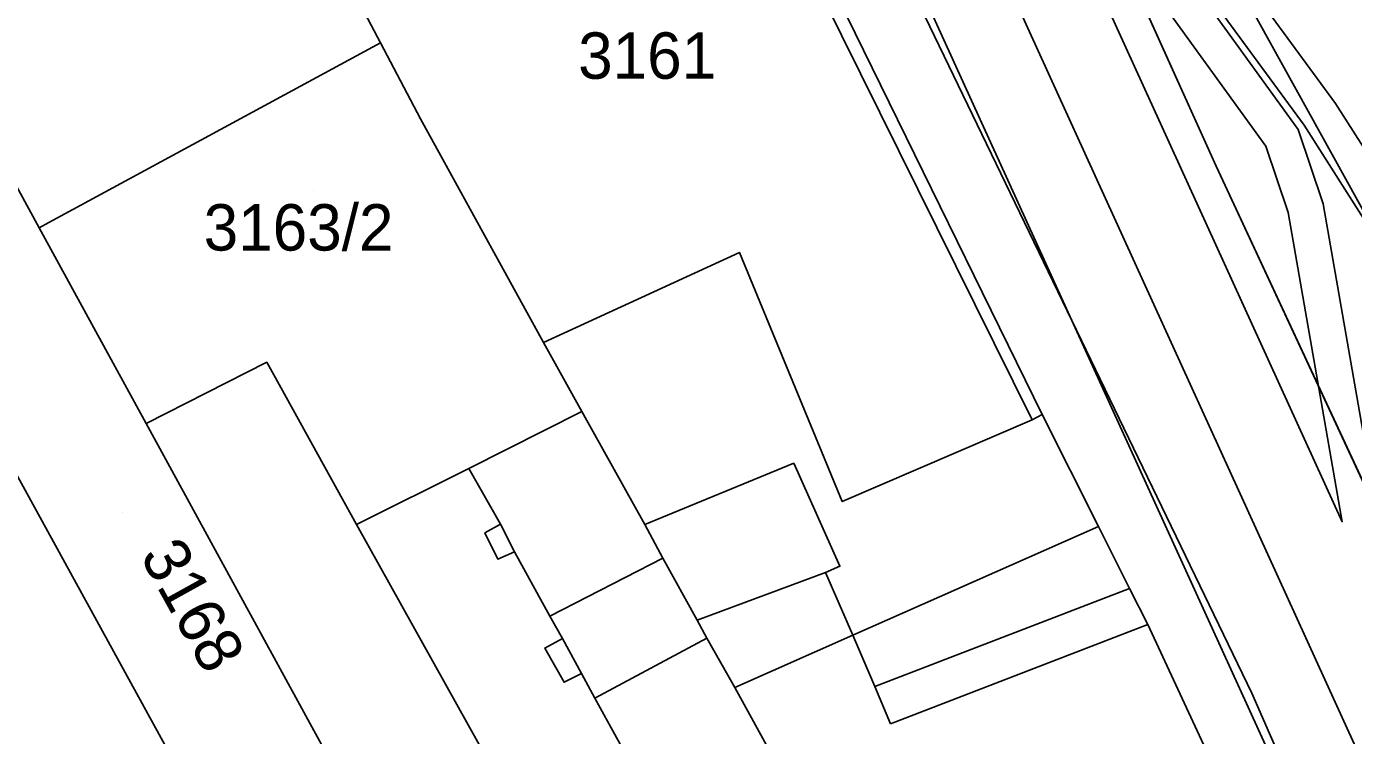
# Model space of a CAD drawing. Extents: x -264070 to -262271, y -1238894 to -1238141.
# Drawn here: x -262970.7 to -262913.5, y -1238536.4 to -1238505.8 of the extents above; entities that cross this region are included whole.
import ezdxf

# ---------------------------------------------------------------- set-up
doc = ezdxf.new("R2010")
doc.units = 0
for name, color, linetype in [('body_kn', 7, 'Continuous'), ('kladpar_druhypozemkov', 7, 'Continuous'), ('kladpar_hranice', 7, 'Continuous'), ('kladpar_parcelnecisla', 7, 'Continuous'), ('kladpar_plochy', 7, 'Continuous'), ('tarchy_linie', 7, 'Continuous'), ('zappar_hrandruhpozemk', 7, 'Continuous')]:
    doc.layers.add(name, color=color, linetype=linetype)

msp = doc.modelspace()

# ---------------------------------------------------------------- linework, layer by layer
at = {"layer": 'body_kn'}
for p, q in [((-262955.44, -1238506.52), (-262955.44, -1238506.52)), ((-262955.44, -1238506.52), (-262955.44, -1238506.52)), ((-262914.29, -1238509.13), (-262914.29, -1238509.13)), ((-262953.72, -1238509.79), (-262953.72, -1238509.79)), ((-262915.89, -1238510.25), (-262915.89, -1238510.25)), ((-262915.64, -1238510.07), (-262915.64, -1238510.07)), ((-262917.28, -1238510.97), (-262917.28, -1238510.97)), ((-262919.42, -1238511.83), (-262919.42, -1238511.83)), ((-262914.81, -1238513.45), (-262914.81, -1238513.45)), ((-262969.73, -1238514.26), (-262969.73, -1238514.26)), ((-262916.32, -1238513.83), (-262916.32, -1238513.83)), ((-262970.15, -1238514.49), (-262970.15, -1238514.49)), ((-262939.97, -1238515.55), (-262939.97, -1238515.55)), ((-262968.71, -1238517.12), (-262968.71, -1238517.12)), ((-262948.41, -1238519.43), (-262948.41, -1238519.43)), ((-262960.34, -1238520.28), (-262960.34, -1238520.28)), ((-262965.54, -1238522.92), (-262965.54, -1238522.92)), ((-262965.54, -1238522.92), (-262965.54, -1238522.92)), ((-262946.76, -1238522.4), (-262946.76, -1238522.4)), ((-262927.36, -1238522.76), (-262927.36, -1238522.76)), ((-262927.36, -1238522.76), (-262927.36, -1238522.76)), ((-262926.92, -1238522.53), (-262926.92, -1238522.53)), ((-262926.92, -1238522.53), (-262926.92, -1238522.53)), ((-262937.63, -1238524.63), (-262937.63, -1238524.63)), ((-262951.63, -1238524.86), (-262951.63, -1238524.86)), ((-262935.54, -1238526.28), (-262935.54, -1238526.28)), ((-262956.47, -1238527.27), (-262956.47, -1238527.27)), ((-262956.47, -1238527.27), (-262956.47, -1238527.27)), ((-262950.27, -1238527.25), (-262950.27, -1238527.25)), ((-262950.27, -1238527.25), (-262950.27, -1238527.25)), ((-262944.05, -1238527.27), (-262944.05, -1238527.27)), ((-262944.05, -1238527.27), (-262944.05, -1238527.27)), ((-262924.5, -1238527.35), (-262924.5, -1238527.35)), ((-262913.99, -1238527.15), (-262913.99, -1238527.15)), ((-262950.94, -1238527.63), (-262950.94, -1238527.63)), ((-262949.66, -1238528.44), (-262949.66, -1238528.44)), ((-262950.39, -1238528.76), (-262950.39, -1238528.76)), ((-262943.28, -1238528.72), (-262943.28, -1238528.72)), ((-262935.64, -1238529.07), (-262935.64, -1238529.07)), ((-262936.26, -1238529.33), (-262936.26, -1238529.33)), ((-262923.16, -1238530.02), (-262923.16, -1238530.02)), ((-262923.16, -1238530.02), (-262923.16, -1238530.02)), ((-262948.14, -1238531.21), (-262948.14, -1238531.21)), ((-262948.14, -1238531.21), (-262948.14, -1238531.21)), ((-262941.8, -1238531.39), (-262941.8, -1238531.39)), ((-262941.8, -1238531.39), (-262941.8, -1238531.39)), ((-262935.09, -1238532.04), (-262935.09, -1238532.04)), ((-262922.37, -1238531.58), (-262922.37, -1238531.58)), ((-262948.36, -1238532.59), (-262948.36, -1238532.59)), ((-262947.6, -1238532.18), (-262947.6, -1238532.18)), ((-262947.6, -1238532.18), (-262947.6, -1238532.18)), ((-262941.38, -1238532.17), (-262941.38, -1238532.17)), ((-262946.78, -1238533.69), (-262946.78, -1238533.69)), ((-262947.53, -1238534.06), (-262947.53, -1238534.06)), ((-262940.17, -1238534.29), (-262940.17, -1238534.29)), ((-262940.17, -1238534.29), (-262940.17, -1238534.29)), ((-262934.14, -1238534.24), (-262934.14, -1238534.24)), ((-262946.21, -1238534.75), (-262946.21, -1238534.75)), ((-262946.21, -1238534.75), (-262946.21, -1238534.75)), ((-262917.89, -1238534.54), (-262917.89, -1238534.54)), ((-262933.46, -1238535.86), (-262933.46, -1238535.86))]:
    msp.add_line(p, q, dxfattribs=at)
at = {"layer": 'kladpar_druhypozemkov'}
for p, q in [((-262958.33, -1238512.87), (-262958.33, -1238512.87)), ((-262966.55, -1238526.77), (-262966.55, -1238526.77))]:
    msp.add_line(p, q, dxfattribs=at)
at = {"layer": 'kladpar_hranice'}
for points in [[(-263001.91, -1238356.1), (-262980.46, -1238391.76), (-262968.09, -1238412.47), (-262957.85, -1238431.45), (-262958.52, -1238431.77), (-262946.12, -1238456.17), (-262944.09, -1238459.15), (-262938.08, -1238472.48), (-262924.76, -1238500.02), (-262919.42, -1238511.83), (-262907.79, -1238536.85)], [(-262907.79, -1238536.85), (-262919.42, -1238511.83), (-262924.76, -1238500.02), (-262938.08, -1238472.48), (-262944.09, -1238459.15)], [(-262917.94, -1238541.14), (-262922.37, -1238531.58), (-262923.16, -1238530.02), (-262924.5, -1238527.35), (-262926.92, -1238522.53), (-262945.99, -1238483.66), (-262950.49, -1238474.92), (-262951.58, -1238472.83), (-262953.1, -1238469.57), (-262953.6, -1238468.49), (-262957.3, -1238460.54)], [(-262926.92, -1238522.53), (-262927.36, -1238522.76), (-262935.54, -1238526.28), (-262939.97, -1238515.55), (-262948.41, -1238519.43), (-262953.72, -1238509.79), (-262955.44, -1238506.52), (-262963.01, -1238492.17), (-262946.6, -1238483.96), (-262945.99, -1238483.66), (-262926.92, -1238522.53)], [(-262963.01, -1238492.17), (-262955.44, -1238506.52), (-262969.73, -1238514.26), (-262970.15, -1238514.49), (-262978.09, -1238499.9), (-262963.01, -1238492.17)], [(-262965.54, -1238522.92), (-262953.9, -1238544.21), (-262948.69, -1238553.63), (-262954.24, -1238555.81), (-262956.57, -1238556.72), (-262964.72, -1238559.53), (-262969.49, -1238550.26), (-262970.29, -1238548.72), (-262970.58, -1238548.19), (-262985.04, -1238522.41), (-262993.38, -1238507.47), (-262988.04, -1238504.92), (-262982.69, -1238502.27), (-262978.09, -1238499.9), (-262970.15, -1238514.49), (-262968.71, -1238517.12), (-262965.54, -1238522.92)], [(-262955.44, -1238506.52), (-262953.72, -1238509.79), (-262948.41, -1238519.43), (-262946.76, -1238522.4), (-262951.63, -1238524.86), (-262956.47, -1238527.27), (-262960.34, -1238520.28), (-262965.54, -1238522.92), (-262968.71, -1238517.12), (-262970.15, -1238514.49), (-262969.73, -1238514.26), (-262955.44, -1238506.52)], [(-262927.36, -1238522.76), (-262926.92, -1238522.53), (-262924.5, -1238527.35), (-262923.16, -1238530.02), (-262922.37, -1238531.58), (-262917.94, -1238541.14), (-262933.09, -1238547.18), (-262940.17, -1238534.29), (-262941.38, -1238532.17), (-262941.8, -1238531.39), (-262943.28, -1238528.72), (-262944.05, -1238527.27), (-262946.76, -1238522.4), (-262948.41, -1238519.43), (-262939.97, -1238515.55), (-262935.54, -1238526.28), (-262927.36, -1238522.76)], [(-262941.8, -1238531.39), (-262941.38, -1238532.17), (-262940.17, -1238534.29), (-262933.09, -1238547.18), (-262941.57, -1238550.63), (-262943.7, -1238551.56), (-262948.69, -1238553.63), (-262953.9, -1238544.21), (-262965.54, -1238522.92), (-262960.34, -1238520.28), (-262956.47, -1238527.27), (-262951.63, -1238524.86), (-262946.76, -1238522.4), (-262944.05, -1238527.27), (-262943.28, -1238528.72), (-262941.8, -1238531.39)]]:
    msp.add_lwpolyline(points, dxfattribs=at)
at = {"layer": 'kladpar_plochy'}
for p, q in [((-262919.42, -1238511.83), (-262924.76, -1238500.02)), ((-262907.79, -1238536.85), (-262919.42, -1238511.83))]:
    msp.add_line(p, q, dxfattribs=at)
msp.add_lwpolyline([(-262944.09, -1238459.15), (-262938.08, -1238472.48), (-262924.76, -1238500.02), (-262919.42, -1238511.83), (-262907.79, -1238536.85), (-262915.4, -1238540.18), (-262915.61, -1238540.27), (-262917.94, -1238541.14), (-262922.37, -1238531.58), (-262923.16, -1238530.02), (-262924.5, -1238527.35), (-262926.92, -1238522.53), (-262945.99, -1238483.66), (-262950.49, -1238474.92), (-262951.58, -1238472.83), (-262953.1, -1238469.57), (-262953.6, -1238468.49), (-262957.3, -1238460.54)], dxfattribs=at)
for points in [[(-262926.92, -1238522.53), (-262927.36, -1238522.76), (-262935.54, -1238526.28), (-262939.97, -1238515.55), (-262948.41, -1238519.43), (-262953.72, -1238509.79), (-262955.44, -1238506.52), (-262963.01, -1238492.17), (-262946.6, -1238483.96), (-262945.99, -1238483.66)], [(-262963.01, -1238492.17), (-262955.44, -1238506.52), (-262969.73, -1238514.26), (-262970.15, -1238514.49), (-262978.09, -1238499.9)], [(-262965.54, -1238522.92), (-262953.9, -1238544.21), (-262948.69, -1238553.63), (-262954.24, -1238555.81), (-262956.57, -1238556.72), (-262964.72, -1238559.53), (-262969.49, -1238550.26), (-262970.29, -1238548.72), (-262970.58, -1238548.19), (-262985.04, -1238522.41), (-262993.38, -1238507.47), (-262988.04, -1238504.92), (-262982.69, -1238502.27), (-262978.09, -1238499.9), (-262970.15, -1238514.49), (-262968.71, -1238517.12)], [(-262955.44, -1238506.52), (-262953.72, -1238509.79), (-262948.41, -1238519.43), (-262946.76, -1238522.4), (-262951.63, -1238524.86), (-262956.47, -1238527.27), (-262960.34, -1238520.28), (-262965.54, -1238522.92), (-262968.71, -1238517.12), (-262970.15, -1238514.49), (-262969.73, -1238514.26)], [(-262927.36, -1238522.76), (-262926.92, -1238522.53), (-262924.5, -1238527.35), (-262923.16, -1238530.02), (-262922.37, -1238531.58), (-262917.94, -1238541.14), (-262933.09, -1238547.18), (-262940.17, -1238534.29), (-262941.38, -1238532.17), (-262941.8, -1238531.39), (-262943.28, -1238528.72), (-262944.05, -1238527.27), (-262946.76, -1238522.4), (-262948.41, -1238519.43), (-262939.97, -1238515.55), (-262935.54, -1238526.28)], [(-262941.8, -1238531.39), (-262941.38, -1238532.17), (-262940.17, -1238534.29), (-262933.09, -1238547.18), (-262941.57, -1238550.63), (-262943.7, -1238551.56), (-262948.69, -1238553.63), (-262953.9, -1238544.21), (-262965.54, -1238522.92), (-262960.34, -1238520.28), (-262956.47, -1238527.27), (-262951.63, -1238524.86), (-262946.76, -1238522.4), (-262944.05, -1238527.27), (-262943.28, -1238528.72)]]:
    msp.add_lwpolyline(points, close=True, dxfattribs=at)
at = {"layer": 'tarchy_linie'}
for points in [[(-263038.59, -1238278.01), (-263038.81, -1238283.6), (-263023.76, -1238334.4), (-263004.35, -1238368.98), (-262988.5, -1238396.63), (-262970, -1238425.7), (-262949.59, -1238461.67), (-262929.74, -1238490.84), (-262915.64, -1238510.07), (-262911.62, -1238516.37), (-262904.25, -1238532.08), (-262899.49, -1238561.55), (-262883.46, -1238603.14), (-262855.12, -1238679.37), (-262825.32, -1238749.06), (-262831.6, -1238762.46)], [(-263049.81, -1238282.44), (-263016.2, -1238342.64), (-262978.3, -1238405.77), (-262957.24, -1238440.79), (-262909.76, -1238544.87), (-262886.28, -1238607.09), (-262862.09, -1238671.7), (-262834.14, -1238746.5), (-262835.49, -1238761.73)], [(-263055.03, -1238285.01), (-263051.32, -1238292.29), (-263037.9, -1238316.25), (-263024.35, -1238337.09), (-262999.02, -1238379.63), (-262988.72, -1238396.66), (-262981.15, -1238408.68), (-262970.2, -1238425.82), (-262949.94, -1238461.94), (-262926.84, -1238495.4), (-262921.43, -1238502.6), (-262915.89, -1238510.25), (-262914.81, -1238513.45), (-262908.31, -1238550.69), (-262885.94, -1238597.77), (-262863.52, -1238671.22), (-262830.98, -1238762.57)], [(-262954.14, -1238439.16), (-262936.28, -1238478.3), (-262928.47, -1238489.78), (-262914.29, -1238509.13), (-262910.17, -1238515.57)], [(-262911.43, -1238550.37), (-262914.01, -1238548.52), (-262914.89, -1238548.89), (-262915.51, -1238547.31), (-262916.4, -1238545.02), (-262916.75, -1238544.13), (-262916.97, -1238543.57), (-262916.09, -1238543.2), (-262913.89, -1238544.78), (-262913.69, -1238544.7), (-262915.69, -1238540.3), (-262915.61, -1238540.27), (-262916.41, -1238538.73), (-262942.71, -1238481.07), (-262940.64, -1238479.43), (-262947.17, -1238470.61), (-262948.78, -1238467.76), (-262950.68, -1238463.6)], [(-262922.68, -1238503.52), (-262917.28, -1238510.97), (-262916.32, -1238513.83), (-262913.99, -1238527.15), (-262928.02, -1238496.41), (-262922.68, -1238503.52)]]:
    msp.add_lwpolyline(points, dxfattribs=at)
at = {"layer": 'zappar_hrandruhpozemk'}
for p, q in [((-262946.6, -1238483.96), (-262927.36, -1238522.76)), ((-262929.65, -1238483.83), (-262910.93, -1238517.66)), ((-262980.04, -1238508.9), (-262960.64, -1238544.21)), ((-262950.27, -1238527.25), (-262951.63, -1238524.86)), ((-262956.47, -1238527.27), (-262948.32, -1238541.89)), ((-262949.66, -1238528.44), (-262950.27, -1238527.25)), ((-262948.14, -1238531.21), (-262943.28, -1238528.72)), ((-262936.26, -1238529.33), (-262941.8, -1238531.39)), ((-262923.16, -1238530.02), (-262934.14, -1238534.24)), ((-262933.46, -1238535.86), (-262922.37, -1238531.58)), ((-262946.78, -1238533.69), (-262947.6, -1238532.18)), ((-262946.21, -1238534.75), (-262941.38, -1238532.17)), ((-262917.89, -1238534.54), (-262915.4, -1238540.18))]:
    msp.add_line(p, q, dxfattribs=at)
for points in [[(-262954.23, -1238460.19), (-262942.37, -1238484.18), (-262934.63, -1238499.88), (-262917.89, -1238534.54)], [(-262944.05, -1238527.27), (-262937.63, -1238524.63), (-262935.64, -1238529.07), (-262936.26, -1238529.33)], [(-262949.66, -1238528.44), (-262950.39, -1238528.76), (-262950.94, -1238527.63), (-262950.27, -1238527.25)], [(-262940.17, -1238534.29), (-262935.09, -1238532.04), (-262924.5, -1238527.35)], [(-262947.6, -1238532.18), (-262948.14, -1238531.21), (-262949.66, -1238528.44)], [(-262936.26, -1238529.33), (-262935.09, -1238532.04), (-262934.14, -1238534.24), (-262933.46, -1238535.86)], [(-262946.78, -1238533.69), (-262947.53, -1238534.06), (-262948.36, -1238532.59), (-262947.6, -1238532.18)], [(-262948.32, -1238541.89), (-262947.79, -1238541.67), (-262945.61, -1238540.74), (-262943.4, -1238539.83), (-262946.21, -1238534.75), (-262946.78, -1238533.69)]]:
    msp.add_lwpolyline(points, dxfattribs=at)

# ---------------------------------------------------------------- texts
at = {"layer": 'kladpar_parcelnecisla'}
for s, p in [('3161', (-262946.923, -1238508.07)), ('3163/2', (-262963.062, -1238515.47))]:
    msp.add_text(s, height=2, dxfattribs=at).set_placement(p)
msp.add_text('3168', height=2, rotation=299, dxfattribs=at).set_placement((-262965.835, -1238528.613))

doc.saveas('drawing.dxf')
